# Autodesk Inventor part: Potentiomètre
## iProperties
Author: Philippe
Created: 2002-01
Part Number: Potentiomètre
Material: Par défaut
Document SubType Name: Modélisation
Designer: Philippe
Control State: 0
Master: False
Checked Out: False
PropertySet Name: Design Tracking Control
Shininess: 59.0
Angle Display Precision: 2
Document Length Units: 11269
Document Angle Units: 11283
Document Time Units: 11279
Document Mass Units: 11290
Document Length Units Precision: 3
Document Angle Units Precision: 2
Compacted: False
PropertySet Name: _Private Model Information
Density: 0.0
Volumn: 0.0
Area: 0.0
PropertySet Name: Model Information
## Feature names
1. Révolution1 [Revolution]
2. Extrusion1
